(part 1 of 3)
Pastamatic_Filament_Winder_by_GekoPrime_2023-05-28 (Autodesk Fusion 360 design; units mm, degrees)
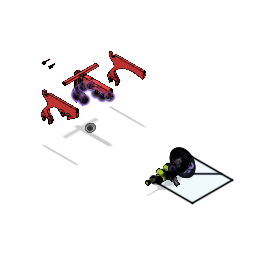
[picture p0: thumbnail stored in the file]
description: Spur Gear; Module: 2.0; Num Teeth: 20; Pressure Angle: 20.0; Backlash: 0.00 mm
description: Spur Gear; Module: 2.0; Num Teeth: 40; Pressure Angle: 20.0; Backlash: 0.00 mm
description: Spur Gear; Module: 2.0; Num Teeth: 10; Pressure Angle: 20.0; Backlash: 0.00 mm
description: Spur Gear; Module: 2.0; Num Teeth: 50; Pressure Angle: 20.0; Backlash: 0.00 mm
description: Spur Gear; Module: 2.0; Num Teeth: 30; Pressure Angle: 20.0; Backlash: 0.00 mm
parameter "bearing_od" = 22
parameter "bearing_id" = 8
parameter "bearing_z" = 7
parameter "spool_id_min" = 50
parameter "spool_id_max" = 60
parameter "spool_od_max" = 250
parameter "spool_z_max" = 120
parameter "ptfe_od" = 4
parameter "drive_span" = 6.65 (= "clearance_loose + 1 / 4 * 1 in")
parameter "overhang_angle" = 45
parameter "spool_z_min" = 50
parameter "spur_gear_z" = 7 (= "bearing_z")
parameter "spur_gear_diameter_medium" = 40
parameter "axle_od" = 26 (= "bearing_od + 2 * wall_thickness")
parameter "leadscrew_pitch" = 30 (= "spool_inner_z_bambu / leadscrew_turns")
parameter "leadscrew_tooth_height" = 3.3333 (= "leadscrew_od / 6")
parameter "clearance_loose" = 0.3
parameter "screw_od" = 22 (= "axle_od - 2 * wall_thickness")
parameter "screw_pitch" = 22 (= "screw_od")
parameter "screw_id" = 18 (= "screw_od - 2 * wall_thickness")
parameter "wall_thickness" = 2
parameter "washer_z" = 0.3 (= "clearance_loose")
parameter "leadscrew_angle" = 64.477 (= "atan(PI * leadscrew_od / leadscrew_pitch)")
parameter "washer_radial_thichness" = 1
parameter "internal_cavity_thickness" = 1
parameter "clearance_tight" = 0.01
parameter "buildplate_limit" = 240
parameter "spur_gear_diameter_small" = 20
parameter "stack_unit" = 11.6 (= "bearing_z + 2 * washer_z + 2 * wall_thickness")
parameter "fillet_radius" = 2 (= "wall_thickness")
parameter "spur_gear_diameter_large" = 100
parameter "ground_clearance" = 20
parameter "drive_depth" = 25.4
parameter "spool_id_bambu" = 54
parameter "spool_od_bambu" = 200
parameter "spool_inner_z_bambu" = 60
parameter "leadscrew_od" = 20
parameter "crossbar_od" = 20 (= "ground_clearance")
parameter "leadscrew_length" = 200
parameter "leadscrew_center_position" = 68.928
parameter "spur_gear_clearance" = 4
parameter "motor_mounting_circle" = 31
parameter "washer_taper" = -45
parameter "spool_interface_z_bambu" = 62
sketch "Sketch1" plane through (0, 0, 0) normal (0, 0, 1) x axis (1, 0, 0)
  circle C1 centre (0, 0) radius 7.5492
extrude "Extrude1" new body sketch "Sketch1" along normal blind 7 bodies "spur_gear_10t_7mm"
sketch "Sketch2" plane through (0, 0, 0) normal (0, 0, 1) x axis (1, 0, 0)
  curve K1 (11.9856, -0.5875) -> (9.2583, -1.6082)
  curve K2 (11.9856, 0.5875) -> (9.2583, 1.6082)
  line L1 (9.2583, -1.6082) -> (7.428, -1.292)
  line L2 (9.2583, 1.6082) -> (7.428, 1.292)
  line L3 (7.428, 1.292) -> (7.428, -1.292)
  arc A1 centre (0, 0) radius 12 clockwise from (11.9856, 0.5875) to (11.9856, -0.5875)
extrude "Extrude2" add sketch "Sketch2" along normal blind 7
fillet "Fillet1" radius 1
circular_pattern "C-Pattern1" countU 10 TotalAngle 360
sketch "Sketch3" plane through (0, 0, 0) normal (0, 0, 1) x axis (1, 0, 0)
  circle C1 centre (0, 0) radius 10
sketch "Sketch1" plane through (0, 0, 0) normal (0, 0, 1) x axis (1, 0, 0)
  circle C1 centre (0, 0) radius 17.5492
  circle C2 centre (0, 0) radius 11
extrude "Extrude1" new body sketch "Sketch1" along normal blind 7 bodies "idler"
sketch "Sketch2" plane through (0, 0, 0) normal (0, 0, 1) x axis (1, 0, 0)
  curve K1 (21.989, -0.6948) -> (18.7119, -1.7536)
  curve K2 (21.989, 0.6948) -> (18.7119, 1.7536)
  line L1 (18.7119, -1.7536) -> (17.4627, -1.6375)
  line L2 (18.7119, 1.7536) -> (17.4627, 1.6375)
  line L3 (17.4627, 1.6375) -> (17.4627, -1.6375)
  arc A1 centre (0, 0) radius 22 clockwise from (21.989, 0.6948) to (21.989, -0.6948)
extrude "Extrude2" add sketch "Sketch2" along normal blind 7
fillet "Fillet1" radius 1
circular_pattern "C-Pattern1" countU 20 TotalAngle 360
sketch "Sketch3" plane through (0, 0, 0) normal (0, 0, 1) x axis (1, 0, 0)
  circle C1 centre (0, 0) radius 20
sketch "Sketch4" plane through (0, 0, 0) normal (1, 0, 0) x axis (0, 0, -1)
  line L1 (0, -22) -> (0, -21.989)
  line L2 (-7, -22) -> (-7, -21.989)
  line L3 (0, 21.989) -> (0, 22)
  line L4 (-7, 21.989) -> (-7, 22)
  line L5 (-7, -22) -> (0, -22)
  line L6 (-7, 22) -> (-7, -21.989)
  line L7 (0, -21.989) -> (0, 21.989)
  line L8 (-7, 19.652) -> (-4.663, 21.989)
  line L9 (0, 19.652) -> (-2.326, 22)
  line L10 (0, 0) -> (-7, 0.0055)
  line L11 (-3.5, 22) -> (-3.5, 19.652)
  line L12 (0, 19.652) -> (-3.5, 19.652)
  line L13 (-7, 19.652) -> (-3.5, 19.652)
  line L14 (-2.326, 22) -> (-4.663, 21.989)
  line L15 (0, 22) -> (-2.326, 22)
  line L16 (-7, 21.989) -> (-4.663, 21.989)
  point P4 (-7, -21.989)
  point P10 (-7, -21.989)
  point P9 (-7, 22)
  point P11 (-7, 22)
  point P6 (0, 21.989)
  point P12 (0, 21.989)
  point P2 (0, -21.989)
  point P13 (0, -21.989)
  point P15 (-7, 19.652)
  point P17 (0, 19.652)
  point P18 (-7, 0.0055)
  point P1 (0, 0)
  point P19 (0, 0)
  point P8 (0, 22)
  point P22 (0, 22)
  point P7 (-7, 21.989)
  point P23 (-7, 21.989)
  coincident P4 P10
  coincident P9 P11
  coincident P6 P12
  coincident P2 P13
  coincident L6 P15
  coincident L7 P17
  midpoint L6 P18
  coincident P1 P19
  equal L8 L9
  perpendicular L7 L12
  perpendicular L6 L13
  perpendicular L11 L12
  coincident P8 P22
  coincident P7 P23
  perpendicular L7 L15
  perpendicular L6 L16
  equal L12 L13
  equal L14 L16
  dimension "d1268" angle L6 L8 = 45
revolve "Revolve1" sketch "Sketch4" AlongAngle 360
chamfer "Chamfer1" distance 1
sketch "Sketch1" plane through (0, 0, 0) normal (0, 0, 1) x axis (1, 0, 0)
  circle C1 centre (0, 0) radius 37.5492
  circle C2 centre (0, 0) radius 11
extrude "Extrude1" new body sketch "Sketch1" along normal blind 7 bodies "spur_gear_40t_7mm"
sketch "Sketch2" plane through (0, 0, 0) normal (0, 0, 1) x axis (1, 0, 0)
  curve K1 (41.9931, -0.7606) -> (37.5326, -2.0353)
  curve K2 (41.9931, 0.7606) -> (37.5326, 2.0353)
  line L1 (37.5326, -2.0353) -> (37.4841, -2.0332)
  line L2 (37.5326, 2.0353) -> (37.4841, 2.0332)
  line L3 (37.4841, 2.0332) -> (37.4841, -2.0332)
  arc A1 centre (0, 0) radius 42 clockwise from (41.9931, 0.7606) to (41.9931, -0.7606)
extrude "Extrude2" add sketch "Sketch2" along normal blind 7
fillet "Fillet1" radius 1
circular_pattern "C-Pattern1" countU 40 TotalAngle 360
sketch "Sketch3" plane through (0, 0, 0) normal (0, 0, 1) x axis (1, 0, 0)
  circle C1 centre (0, 0) radius 40
sketch "Sketch1" plane through (0, 0, 0) normal (0, 0, 1) x axis (1, 0, 0)
  circle C1 centre (0, 0) radius 47.5492
extrude "Extrude1" new body sketch "Sketch1" along normal blind 7 bodies "spur_gear_50t_7mm"
sketch "Sketch2" plane through (0, 0, 0) normal (0, 0, 1) x axis (1, 0, 0)
  curve K1 (51.9942, -0.7754) -> (46.9342, -2.1756)
  curve K2 (51.9942, 0.7754) -> (46.9342, 2.1756)
  line L1 (46.9342, -2.1756) -> (46.9342, 2.1756)
  arc A1 centre (0, 0) radius 52 clockwise from (51.9942, 0.7754) to (51.9942, -0.7754)
extrude "Extrude2" add sketch "Sketch2" along normal blind 7
fillet "Fillet1" radius 1
circular_pattern "C-Pattern1" countU 50 TotalAngle 360
sketch "Sketch3" plane through (0, 0, 0) normal (0, 0, 1) x axis (1, 0, 0)
  circle C1 centre (0, 0) radius 50
sketch "Sketch5" plane through (0, 0, 0) normal (1, 0, 0) x axis (0, 0, -1)
  line L1 (-7, 51.9403) -> (0, 51.9403)
  line L2 (0, 49.607) -> (-3.5, 53.107)
  line L3 (0, 51.9403) -> (0, 49.607)
  line L4 (-7, 49.607) -> (-7, 51.9403)
  line L5 (-3.5, 53.107) -> (-7, 49.607)
  line L6 (-7, 53.107) -> (-7, 51.9403)
  line L7 (0, 53.107) -> (-7, 53.107)
  line L8 (0, 51.9403) -> (0, 53.107)
  point P2 (0, 51.9403)
  point P6 (0, 51.9403)
  point P3 (-7, 51.9403)
  point P7 (-7, 51.9403)
  point P10 (-7, 51.9403)
  point P13 (0, 51.9403)
  point P14 (-4.6667, 51.9403)
  point P15 (-2.3333, 51.9403)
  point P9 (-3.5, 53.107)
  point P4 (-3.5, 53.107)
  coincident P2 P6
  coincident P3 P7
  perpendicular L1 L4
  perpendicular L1 L3
  equal L2 L5
  equal L3 L4
  coincident P3 P10
  perpendicular L1 L6
  coincident P2 P13
  perpendicular L1 L8
  coincident L5 P14
  coincident L1 P14
  coincident L1 P15
  coincident L2 P15
  perpendicular L6 L7
  coincident P9 L7
  coincident P4 L7
  coincident P4 P9
  dimension "d1416" angle L4 L5 = 45
  dimension "d1419" distance P14 P15 = 2.3333 (= "bearing_z / 3")
revolve "Revolve1" sketch "Sketch5" AlongAngle 360
sketch "Sketch1" plane through (0, 0, 0) normal (0, 0, 1) x axis (1, 0, 0)
  line L1 (1.6583, -2.5) -> (-1.6583, -2.5)
  line L2 (4, 3) -> (-5, 3)
  circle C1 centre (0, 0) radius 7.5492
  circle C2 centre (0, 0) radius 3
  point P4 (-1.6583, -2.5)
  point P5 (1.6583, -2.5)
  concentric C1 C2
  coincident C2 P4
  coincident C2 P5
  horizontal L1
  horizontal L2
  tangent C2 L2
  dimension "d1565" distance L1 L2 = 5.5
  dimension "d1566" diameter C2 = 6
extrude "Extrude1" new body sketch "Sketch1" profile of C1 C2 L1 along normal blind 14 named "d988_1" bodies "spur_gear_10t_14mm_6mmD"
sketch "Sketch2" plane through (0, 0, 0) normal (0, 0, 1) x axis (1, 0, 0)
  curve K1 (11.9856, -0.5875) -> (9.2583, -1.6082)
  curve K2 (11.9856, 0.5875) -> (9.2583, 1.6082)
  line L1 (9.2583, -1.6082) -> (7.428, -1.292)
  line L2 (9.2583, 1.6082) -> (7.428, 1.292)
  line L3 (7.428, 1.292) -> (7.428, -1.292)
  arc A1 centre (0, 0) radius 12 clockwise from (11.9856, 0.5875) to (11.9856, -0.5875)
extrude "Extrude2" add sketch "Sketch2" along normal blind 14 named "d990_1"
fillet "Fillet1" radius 1 named "d993_1"
circular_pattern "C-Pattern1" countU 10 named "d994_1" TotalAngle 360 named "d995_1"
sketch "Sketch3" plane through (0, 0, 0) normal (0, 0, 1) x axis (1, 0, 0)
  circle C1 centre (0, 0) radius 10
sketch "Sketch4" plane through (0, 0, 0) normal (0, 1, 0) x axis (1, 0, 0)
  line L1 (0, 0) -> (0, -14)
  line L2 (9.6667, 0) -> (0, 0)
  line L3 (12, -2.3333) -> (9.6667, 0)
  line L4 (12, -11.6667) -> (12, -2.3333)
  line L5 (9.6667, -14) -> (12, -11.6667)
  line L6 (0, -14) -> (9.6667, -14)
  line L7 (0, -7) -> (12, -7)
  point P1 (0, 0)
  point P3 (0, 0)
  point P8 (12, -7)
  point P9 (0, -7)
  point P2 (0, -14)
  point P5 (12, -2.3333)
  point P6 (12, -11.6667)
  coincident P1 P3
  vertical L1
  perpendicular L1 L2
  perpendicular L2 L4
  perpendicular L1 L6
  equal L3 L5
  midpoint L4 P8
  midpoint L1 P9
  perpendicular L4 L7
  dimension "d1567" distance P2 P3 = 14
  dimension "d1568" distance L1 L4 = 12 (= "spur_gear_diameter_small / 2 + spur_gear_clearance / 2")
  dimension "d1569" angle L5 L6 = 45
  dimension "d1570" distance P5 P6 = 9.3333 (= "7 mm + ( 7 / 3 ) * 1 mm")
revolve "Revolve1" sketch "Sketch4" AlongAngle 360
sketch "Sketch1" plane through (0, 0, 0) normal (0, 0, 1) x axis (1, 0, 0)
  circle C1 centre (0, 0) radius 27.5492
extrude "Extrude1" new body sketch "Sketch1" along normal blind 7 bodies "spur_gear_30t_7mm"
sketch "Sketch2" plane through (0, 0, 0) normal (0, 0, 1) x axis (1, 0, 0)
  curve K1 (31.9915, -0.7373) -> (28.127, -1.8948)
  curve K2 (31.9915, 0.7373) -> (28.127, 1.8948)
  line L1 (28.127, -1.8948) -> (27.4769, -1.8517)
  line L2 (28.127, 1.8948) -> (27.4769, 1.8517)
  line L3 (27.4769, 1.8517) -> (27.4769, -1.8517)
  arc A1 centre (0, 0) radius 32 clockwise from (31.9915, 0.7373) to (31.9915, -0.7373)
extrude "Extrude2" add sketch "Sketch2" along normal blind 7
fillet "Fillet1" radius 1
circular_pattern "C-Pattern1" countU 30 TotalAngle 360
sketch "Sketch3" plane through (0, 0, 0) normal (0, 0, 1) x axis (1, 0, 0)
  circle C1 centre (0, 0) radius 30
copy_paste_bodies "CopyPasteBodies3"
copy_paste_bodies "CopyPasteBodies2"
align "Align1"
move "Move1" TranslateX 0 TranslateY 0 TranslateZ -4 (= "-2 * wall_thickness")
sketch "Sketch1" plane through (0, 0, 7) normal (0, 0, 1) x axis (1, 0, 0)
  curve K1 (27.4076, 2.7893) -> (28.3353, 1.8928)
  curve K2 (31.9915, 0.7373) -> (28.3353, 1.8928)
  curve K3 (28.3353, -1.8928) -> (31.9915, -0.7373)
  curve K4 (28.3353, -1.8928) -> (27.4076, -2.7893)
  curve K5 (27.3886, -2.97) -> (28.1096, -4.0398)
  curve K6 (31.4457, -5.9302) -> (28.1096, -4.0398)
  curve K7 (27.3226, -7.7427) -> (31.1391, -7.3726)
  curve K8 (27.3226, -7.7427) -> (26.2288, -8.4267)
  curve K9 (26.1726, -8.5996) -> (26.6554, -9.7959)
  curve K10 (29.5256, -12.3385) -> (26.6554, -9.7959)
  curve K11 (25.1157, -13.2541) -> (28.9258, -13.6857)
  curve K12 (25.1157, -13.2541) -> (23.9036, -13.6958)
  curve K13 (23.8127, -13.8532) -> (24.0363, -15.1238)
  curve K14 (26.3151, -18.2076) -> (24.0363, -15.1238)
  curve K15 (21.8112, -18.1864) -> (25.4483, -19.4007)
  curve K16 (21.8112, -18.1864) -> (20.5337, -18.3664)
  curve K17 (20.4121, -18.5015) -> (20.3666, -19.7907)
  curve K18 (21.9544, -23.2809) -> (20.3666, -19.7907)
  curve K19 (17.5534, -22.3237) -> (20.8585, -24.2677)
  curve K20 (17.5534, -22.3237) -> (16.2665, -22.2342)
  curve K21 (16.1194, -22.3411) -> (15.8068, -23.5927)
  curve K22 (16.6343, -27.3368) -> (15.8068, -23.5927)
  curve K23 (12.5284, -25.4855) -> (15.3572, -28.0741)
  curve K24 (12.5284, -25.4855) -> (11.2882, -25.1303)
  curve K25 (11.1222, -25.2043) -> (10.5562, -26.3636)
  curve K26 (10.5872, -30.1979) -> (10.5562, -26.3636)
  curve K27 (6.9559, -27.5334) -> (9.1847, -30.6536)
  curve K28 (6.9559, -27.5334) -> (5.8167, -26.9281)
  curve K29 (5.6389, -26.9659) -> (4.8443, -27.9822)
  curve K30 (4.0773, -31.7392) -> (4.8443, -27.9822)
  curve K31 (1.0794, -28.3779) -> (2.6107, -31.8933)
  curve K32 (1.0794, -28.3779) -> (0.0909, -27.5491)
  curve K33 (-0.0909, -27.5491) -> (-1.0794, -28.3779)
  curve K34 (-2.6107, -31.8933) -> (-1.0794, -28.3779)
  curve K35 (-4.8443, -27.9822) -> (-4.0773, -31.7392)
  curve K36 (-4.8443, -27.9822) -> (-5.6389, -26.9659)
  curve K37 (-5.8167, -26.9281) -> (-6.9559, -27.5334)
  curve K38 (-9.1847, -30.6536) -> (-6.9559, -27.5334)
  curve K39 (-10.5562, -26.3636) -> (-10.5872, -30.1979)
  curve K40 (-10.5562, -26.3636) -> (-11.1222, -25.2043)
  curve K41 (-11.2882, -25.1303) -> (-12.5284, -25.4855)
  curve K42 (-15.3572, -28.0741) -> (-12.5284, -25.4855)
  curve K43 (-15.8068, -23.5927) -> (-16.6343, -27.3368)
  curve K44 (-15.8068, -23.5927) -> (-16.1194, -22.3411)
  curve K45 (-16.2665, -22.2342) -> (-17.5534, -22.3237)
  curve K46 (-20.8585, -24.2677) -> (-17.5534, -22.3237)
  curve K47 (-20.3666, -19.7907) -> (-21.9544, -23.2809)
  curve K48 (-20.3666, -19.7907) -> (-20.4121, -18.5015)
  curve K49 (-20.5337, -18.3664) -> (-21.8112, -18.1864)
  curve K50 (-25.4483, -19.4007) -> (-21.8112, -18.1864)
  curve K51 (-24.0363, -15.1238) -> (-26.3151, -18.2076)
  curve K52 (-24.0363, -15.1238) -> (-23.8127, -13.8532)
  curve K53 (-23.9036, -13.6958) -> (-25.1157, -13.2541)
  curve K54 (-28.9258, -13.6857) -> (-25.1157, -13.2541)
  curve K55 (-26.6554, -9.7959) -> (-29.5256, -12.3385)
  curve K56 (-26.6554, -9.7959) -> (-26.1726, -8.5996)
  curve K57 (-26.2288, -8.4267) -> (-27.3226, -7.7427)
  curve K58 (-31.1391, -7.3726) -> (-27.3226, -7.7427)
  curve K59 (-28.1096, -4.0398) -> (-31.4457, -5.9302)
  curve K60 (-28.1096, -4.0398) -> (-27.3886, -2.97)
  curve K61 (-27.4076, -2.7893) -> (-28.3353, -1.8928)
  curve K62 (-31.9915, -0.7373) -> (-28.3353, -1.8928)
  curve K63 (-28.3353, 1.8928) -> (-31.9915, 0.7373)
  curve K64 (-28.3353, 1.8928) -> (-27.4076, 2.7893)
  curve K65 (-27.3886, 2.97) -> (-28.1096, 4.0398)
  curve K66 (-31.4457, 5.9302) -> (-28.1096, 4.0398)
  curve K67 (-27.3226, 7.7427) -> (-31.1391, 7.3726)
  curve K68 (-27.3226, 7.7427) -> (-26.2288, 8.4267)
  curve K69 (-26.1726, 8.5996) -> (-26.6554, 9.7959)
  curve K70 (-29.5256, 12.3385) -> (-26.6554, 9.7959)
  curve K71 (-25.1157, 13.2541) -> (-28.9258, 13.6857)
  curve K72 (-25.1157, 13.2541) -> (-23.9036, 13.6958)
  curve K73 (-23.8127, 13.8532) -> (-24.0363, 15.1238)
  curve K74 (-26.3151, 18.2076) -> (-24.0363, 15.1238)
  curve K75 (-21.8112, 18.1864) -> (-25.4483, 19.4007)
  curve K76 (-21.8112, 18.1864) -> (-20.5337, 18.3664)
  curve K77 (-20.4121, 18.5015) -> (-20.3666, 19.7907)
  curve K78 (-21.9544, 23.2809) -> (-20.3666, 19.7907)
  curve K79 (-17.5534, 22.3237) -> (-20.8585, 24.2677)
  curve K80 (-17.5534, 22.3237) -> (-16.2665, 22.2342)
  curve K81 (-16.1194, 22.3411) -> (-15.8068, 23.5927)
  curve K82 (-16.6343, 27.3368) -> (-15.8068, 23.5927)
  curve K83 (-12.5284, 25.4855) -> (-15.3572, 28.0741)
  curve K84 (-12.5284, 25.4855) -> (-11.2882, 25.1303)
  curve K85 (-11.1222, 25.2043) -> (-10.5562, 26.3636)
  curve K86 (-10.5872, 30.1979) -> (-10.5562, 26.3636)
  curve K87 (-6.9559, 27.5334) -> (-9.1847, 30.6536)
  curve K88 (-6.9559, 27.5334) -> (-5.8167, 26.9281)
  curve K89 (-5.6389, 26.9659) -> (-4.8443, 27.9822)
  curve K90 (-4.0773, 31.7392) -> (-4.8443, 27.9822)
  curve K91 (-1.0794, 28.3779) -> (-2.6107, 31.8933)
  curve K92 (-1.0794, 28.3779) -> (-0.0909, 27.5491)
  curve K93 (0.0909, 27.5491) -> (1.0794, 28.3779)
  curve K94 (2.6107, 31.8933) -> (1.0794, 28.3779)
  curve K95 (4.8443, 27.9822) -> (4.0773, 31.7392)
  curve K96 (4.8443, 27.9822) -> (5.6389, 26.9659)
  curve K97 (5.8167, 26.9281) -> (6.9559, 27.5334)
  curve K98 (9.1847, 30.6536) -> (6.9559, 27.5334)
  curve K99 (10.5562, 26.3636) -> (10.5872, 30.1979)
  curve K100 (10.5562, 26.3636) -> (11.1222, 25.2043)
  curve K101 (11.2882, 25.1303) -> (12.5284, 25.4855)
  curve K102 (15.3572, 28.0741) -> (12.5284, 25.4855)
  curve K103 (15.8068, 23.5927) -> (16.6343, 27.3368)
  curve K104 (15.8068, 23.5927) -> (16.1194, 22.3411)
  curve K105 (16.2665, 22.2342) -> (17.5534, 22.3237)
  curve K106 (20.8585, 24.2677) -> (17.5534, 22.3237)
  curve K107 (20.3666, 19.7907) -> (21.9544, 23.2809)
  curve K108 (20.3666, 19.7907) -> (20.4121, 18.5015)
  curve K109 (20.5337, 18.3664) -> (21.8112, 18.1864)
  curve K110 (25.4483, 19.4007) -> (21.8112, 18.1864)
  curve K111 (24.0363, 15.1238) -> (26.3151, 18.2076)
  curve K112 (24.0363, 15.1238) -> (23.8127, 13.8532)
  curve K113 (23.9036, 13.6958) -> (25.1157, 13.2541)
  curve K114 (28.9258, 13.6857) -> (25.1157, 13.2541)
  curve K115 (26.6554, 9.7959) -> (29.5256, 12.3385)
  curve K116 (26.6554, 9.7959) -> (26.1726, 8.5996)
  curve K117 (26.2288, 8.4267) -> (27.3226, 7.7427)
  curve K118 (31.1391, 7.3726) -> (27.3226, 7.7427)
  curve K119 (28.1096, 4.0398) -> (31.4457, 5.9302)
  curve K120 (28.1096, 4.0398) -> (27.3886, 2.97)
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  point P1 (0, 0)
  point P2 (0, 0)
  coincident P1 P2
  dimension "d1501" distance = 2 (= "wall_thickness")
  dimension "d1748" diameter = 50.3377 (= "spur_gear_conversion_diameter - 2 * spur_gear_clearance - 2 * wall_thickness")
  dimension "d1749" distance = 2 (= "wall_thickness")
  dimension "d1750" distance = 2 (= "wall_thickness")
  dimension "d1751" angle = 36 (= "( 360 / 10 ) * 1 deg")
extrude "Extrude7" cut sketch "Sketch1" no distance stored
fillet "Fillet2" radius 2 (= "wall_thickness")
chamfer "Chamfer3" distance 0.5 (= "wall_thickness / 4")
circular_pattern "C-Pattern3" countU 10 TotalAngle 360
loft "Loft2" sketch "Sketch1" bodies "spur_gear_30t_7mm"
extrude "Extrude5" cut sketch "Sketch1" no distance stored
sketch "Sketch2" plane through (0, 0, -4) normal (0, 0, -1) x axis (-1, 0, 0)
  line L1 (-4.3904, -8.3082) -> (-3.9672, -7.5055)
  curve K1 (-4.2625, -11.2175) -> (-4.3904, -8.3082)
  curve K2 (-3.145, -11.5805) -> (-1.3315, -9.3021)
  line L2 (-1.2021, -8.404) -> (-1.3315, -9.3021)
  line L3 (1.3315, -9.3021) -> (1.2021, -8.404)
  curve K3 (3.145, -11.5805) -> (1.3315, -9.3021)
  curve K4 (4.2625, -11.2175) -> (4.3904, -8.3082)
  line L4 (3.9672, -7.5055) -> (4.3904, -8.3082)
  line L5 (6.5449, -6.7429) -> (5.9123, -6.0924)
  curve K5 (9.3513, -7.5202) -> (6.5449, -6.7429)
  curve K6 (10.0419, -6.5697) -> (8.4354, -4.1409)
  line L6 (7.6212, -3.7403) -> (8.4354, -4.1409)
  line L7 (9.2583, -1.6082) -> (8.3641, -1.4537)
  curve K7 (11.9856, -0.5875) -> (9.2583, -1.6082)
  curve K8 (11.9856, 0.5875) -> (9.2583, 1.6082)
  line L8 (8.3641, 1.4537) -> (9.2583, 1.6082)
  line L9 (8.4354, 4.1409) -> (7.6212, 3.7403)
  curve K9 (10.0419, 6.5697) -> (8.4354, 4.1409)
  curve K10 (9.3513, 7.5202) -> (6.5449, 6.7429)
  line L10 (5.9123, 6.0924) -> (6.5449, 6.7429)
  line L11 (4.3904, 8.3082) -> (3.9672, 7.5055)
  curve K11 (4.2625, 11.2175) -> (4.3904, 8.3082)
  curve K12 (3.145, 11.5805) -> (1.3315, 9.3021)
  line L12 (1.2021, 8.404) -> (1.3315, 9.3021)
  line L13 (-1.3315, 9.3021) -> (-1.2021, 8.404)
  curve K13 (-3.145, 11.5805) -> (-1.3315, 9.3021)
  curve K14 (-4.2625, 11.2175) -> (-4.3904, 8.3082)
  line L14 (-3.9672, 7.5055) -> (-4.3904, 8.3082)
  line L15 (-6.5449, 6.7429) -> (-5.9123, 6.0924)
  curve K15 (-9.3513, 7.5202) -> (-6.5449, 6.7429)
  curve K16 (-10.0419, 6.5697) -> (-8.4354, 4.1409)
  line L16 (-7.6212, 3.7403) -> (-8.4354, 4.1409)
  line L17 (-9.2583, 1.6082) -> (-8.3641, 1.4537)
  curve K17 (-11.9856, 0.5875) -> (-9.2583, 1.6082)
  curve K18 (-11.9856, -0.5875) -> (-9.2583, -1.6082)
  line L18 (-8.3641, -1.4537) -> (-9.2583, -1.6082)
  line L19 (-8.4354, -4.1409) -> (-7.6212, -3.7403)
  curve K19 (-10.0419, -6.5697) -> (-8.4354, -4.1409)
  curve K20 (-9.3513, -7.5202) -> (-6.5449, -6.7429)
  line L20 (-5.9123, -6.0924) -> (-6.5449, -6.7429)
  arc A1 centre (-4.8518, -7.0391) radius 1 clockwise from (-4.2842, -6.2158) to (-3.9672, -7.5055)
  arc A2 centre (0, 0) radius 12 clockwise from (-3.145, -11.5805) to (-4.2625, -11.2175)
  arc A3 centre (-0.2123, -8.5466) radius 1 clockwise from (-1.2021, -8.404) to (-0.1875, -7.5469)
  arc A4 centre (0, 0) radius 7.5492 clockwise from (0.1875, -7.5469) to (-0.1875, -7.5469)
  arc A5 centre (0.2123, -8.5466) radius 1 clockwise from (0.1875, -7.5469) to (1.2021, -8.404)
  arc A6 centre (0, 0) radius 12 clockwise from (4.2625, -11.2175) to (3.145, -11.5805)
  arc A7 centre (4.8518, -7.0391) radius 1 clockwise from (3.9672, -7.5055) to (4.2842, -6.2158)
  arc A8 centre (0, 0) radius 7.5492 clockwise from (4.5876, -5.9953) to (4.2842, -6.2158)
  arc A9 centre (5.1953, -6.7895) radius 1 clockwise from (4.5876, -5.9953) to (5.9123, -6.0924)
  arc A10 centre (0, 0) radius 12 clockwise from (10.0419, -6.5697) to (9.3513, -7.5202)
  arc A11 centre (8.0626, -2.843) radius 1 clockwise from (7.6212, -3.7403) to (7.1196, -2.5104)
  arc A12 centre (0, 0) radius 7.5492 clockwise from (7.2354, -2.1538) to (7.1196, -2.5104)
  arc A13 centre (8.1939, -2.4391) radius 1 clockwise from (7.2354, -2.1538) to (8.3641, -1.4537)
  arc A14 centre (0, 0) radius 12 clockwise from (11.9856, 0.5875) to (11.9856, -0.5875)
  arc A15 centre (8.1939, 2.4391) radius 1 clockwise from (8.3641, 1.4537) to (7.2354, 2.1538)
  arc A16 centre (0, 0) radius 7.5492 clockwise from (7.1196, 2.5104) to (7.2354, 2.1538)
  arc A17 centre (8.0626, 2.843) radius 1 clockwise from (7.1196, 2.5104) to (7.6212, 3.7403)
  arc A18 centre (0, 0) radius 12 clockwise from (9.3513, 7.5202) to (10.0419, 6.5697)
  arc A19 centre (5.1953, 6.7895) radius 1 clockwise from (5.9123, 6.0924) to (4.5876, 5.9953)
  arc A20 centre (0, 0) radius 7.5492 clockwise from (4.2842, 6.2158) to (4.5876, 5.9953)
  arc A21 centre (4.8518, 7.0391) radius 1 clockwise from (4.2842, 6.2158) to (3.9672, 7.5055)
  arc A22 centre (0, 0) radius 12 clockwise from (3.145, 11.5805) to (4.2625, 11.2175)
  arc A23 centre (0.2123, 8.5466) radius 1 clockwise from (1.2021, 8.404) to (0.1875, 7.5469)
  arc A24 centre (0, 0) radius 7.5492 clockwise from (-0.1875, 7.5469) to (0.1875, 7.5469)
  arc A25 centre (-0.2123, 8.5466) radius 1 clockwise from (-0.1875, 7.5469) to (-1.2021, 8.404)
  arc A26 centre (0, 0) radius 12 clockwise from (-4.2625, 11.2175) to (-3.145, 11.5805)
  arc A27 centre (-4.8518, 7.0391) radius 1 clockwise from (-3.9672, 7.5055) to (-4.2842, 6.2158)
  arc A28 centre (0, 0) radius 7.5492 clockwise from (-4.5876, 5.9953) to (-4.2842, 6.2158)
  arc A29 centre (-5.1953, 6.7895) radius 1 clockwise from (-4.5876, 5.9953) to (-5.9123, 6.0924)
  arc A30 centre (0, 0) radius 12 clockwise from (-10.0419, 6.5697) to (-9.3513, 7.5202)
  arc A31 centre (-8.0626, 2.843) radius 1 clockwise from (-7.6212, 3.7403) to (-7.1196, 2.5104)
  arc A32 centre (0, 0) radius 7.5492 clockwise from (-7.2354, 2.1538) to (-7.1196, 2.5104)
  arc A33 centre (-8.1939, 2.4391) radius 1 clockwise from (-7.2354, 2.1538) to (-8.3641, 1.4537)
  arc A34 centre (0, 0) radius 12 clockwise from (-11.9856, -0.5875) to (-11.9856, 0.5875)
  arc A35 centre (-8.1939, -2.4391) radius 1 clockwise from (-8.3641, -1.4537) to (-7.2354, -2.1538)
  arc A36 centre (0, 0) radius 7.5492 clockwise from (-7.1196, -2.5104) to (-7.2354, -2.1538)
  arc A37 centre (-8.0626, -2.843) radius 1 clockwise from (-7.1196, -2.5104) to (-7.6212, -3.7403)
  arc A38 centre (0, 0) radius 12 clockwise from (-9.3513, -7.5202) to (-10.0419, -6.5697)
  arc A39 centre (-5.1953, -6.7895) radius 1 clockwise from (-5.9123, -6.0924) to (-4.5876, -5.9953)
  arc A40 centre (0, 0) radius 7.5492 clockwise from (-4.2842, -6.2158) to (-4.5876, -5.9953)
  circle C1 centre (0, 0) radius 4.15
  concentric A2 C1
  dimension "d1622" diameter C1 = 8.3 (= "bearing_id + clearance_loose")
loft "Loft3" sketch "Sketch2" + "Sketch1" Start TakeOff Angle 0
sketch "Sketch3" plane through (0, 0, 0) normal (0, 1, 0) x axis (1, 0, 0)
  line L1 (0, -14) -> (-32, -14)
  line L2 (0, 4) -> (0, -14)
  line L3 (-12, 4) -> (0, 4)
  line L4 (-12, -3) -> (-12, 4)
  line L5 (-32, -7) -> (-12, -3)
  line L6 (-32, -14) -> (-32, -7)
  line L7 (-29.6667, -14) -> (-32, -11.6667)
  line L8 (-12, -7) -> (-32, -7)
  line L9 (-12, -3) -> (-12, -7)
  line L10 (-29.6667, -7) -> (-32, -9.3333)
  line L11 (-9.6667, 4) -> (-12, 1.6667)
  point P7 (-32, -7)
  point P8 (0, -7)
  point P9 (-32, -11.6667)
  point P10 (-29.6667, -14)
  point P12 (-32, -9.3333)
  point P13 (-29.6667, -7)
  point P14 (-12, 1.6667)
  point P15 (-9.6667, 4)
  point P5 (-12, 4)
  point P6 (-12, -3)
  point P2 (-32, -14)
  point P4 (0, 4)
  point P3 (0, -14)
  horizontal L1
  perpendicular L1 L2
  perpendicular L2 L3
  perpendicular L3 L4
  perpendicular L1 L6
  horizontal P7 P8
  coincident L2 P8
  coincident L6 P9
  coincident L1 P10
  perpendicular L6 L8
  perpendicular L8 L9
  coincident L6 P12
  coincident L8 P13
  coincident L4 P14
  coincident L3 P15
  equal L7 L10
  equal L10 L11
  perpendicular L7 L10
  parallel L10 L11
  dimension "d1626" distance P5 P6 = 7 (= "bearing_z")
  dimension "d1627" distance P2 P7 = 7 (= "bearing_z")
  dimension "d1628" distance P6 P7 = 4 (= "2 * wall_thickness")
  dimension "d1629" distance P4 P5 = 12 (= "spur_gear_diameter_small / 2 + spur_gear_clearance / 2")
  dimension "d1630" distance P2 P3 = 32 (= "( 60 / 2 ) * 1 mm + spur_gear_clearance / 2")
  dimension "d1631" angle L1 L7 = 45
  dimension "d1632" distance P9 P12 = 2.3333 (= "bearing_z / 3")
revolve "Revolve1" sketch "Sketch3" AlongAngle 360
chamfer "Chamfer2" distance 0.5 (= "wall_thickness / 4")
sketch "Sketch1" plane through (0, 0, 0) normal (0, 0, 1) x axis (1, 0, 0)
  line L1 (0, 5) -> (0, -5)
  line L2 (24.6, -10.3) -> (24.6, 10.3)
  line L3 (49.22, -10.3) -> (24.6, -10.3)
  line L4 (49.22, 10.3) -> (49.22, -10.3)
  line L5 (24.6, 10.3) -> (49.22, 10.3)
  line L6 (49.21, -10.29) -> (24.61, -10.29)
  line L7 (49.21, 10.29) -> (49.21, -10.29)
  line L8 (24.61, 10.29) -> (49.21, 10.29)
  line L9 (24.61, -10.29) -> (24.61, 10.29)
  line L10 (0, -5) -> (24.6, -5)
  line L11 (12.3, 5) -> (12.3, -5)
  line L12 (24.6, 5) -> (0, 5)
  line L13 (24.6, 0) -> (0, 0)
  line L14 (51.21, 12.3) -> (0, 12.3)
  line L15 (51.21, -12.3) -> (51.21, 12.3)
  line L16 (0, -12.3) -> (51.21, -12.3)
  line L17 (66, -55) -> (66, 55)
  line L18 (66, 0) -> (51.21, 0)
  line L19 (-34.4247, 0) -> (0, 0)
  line L20 (-34.4247, 4) -> (-18.4247, 4)
  line L21 (-18.4247, -4) -> (-34.4247, -4)
  circle C1 centre (0, 0) radius 10
  circle C2 centre (0, 0) radius 10.3
  arc A1 centre (-34.4247, 0) radius 4 clockwise from (-34.4247, -4) to (-34.4247, 4)
  circle C3 centre (0, 0) radius 12.3
  arc A2 centre (-18.4247, 16.3) radius 12.3 clockwise from (-9.2124, 8.15) to (-18.4247, 4)
  arc A3 centre (-18.4247, -16.3) radius 12.3 clockwise from (-18.4247, -4) to (-9.2124, -8.15)
  arc A4 centre (62, 40) radius 4 clockwise from (58.7574, 42.3421) to (65.0379, 37.3978)
  arc A5 centre (62, -40) radius 4 clockwise from (65.0378, -37.3978) to (58.7574, -42.3421)
  arc A6 centre (0, -84.7809) radius 72.4809 clockwise from (0, -12.3) to (58.7574, -42.3421)
  arc A7 centre (0, 84.7809) radius 72.4809 clockwise from (58.7574, 42.3421) to (0, 12.3)
  arc A8 centre (108.6956, 0) radius 57.4856 clockwise from (65.0378, -37.3978) to (65.0379, 37.3978)
  point P1 (0, 0)
  point P3 (0, 0)
  point P6 (0, 0)
  point P7 (10.3, 0)
  point P20 (24.6, 0)
  point P21 (24.6, -5)
  point P22 (12.3, -5)
  point P24 (24.6, 5)
  point P23 (12.3, 5)
  point P19 (0, 0)
  point P25 (0, 0)
  point P26 (24.6, 0)
  point P27 (0, 12.3)
  point P30 (0, -12.3)
  point P33 (51.21, 0)
  point P34 (66, 0)
  point P35 (0, 0)
  point P16 (-34.4247, 0)
  point P36 (-34.4247, 0)
  point P39 (-9.2124, 8.15)
  point P41 (-9.2124, -8.15)
  point P55 (108.6956, 0)
  point P51 (0, -12.3)
  point P53 (0, 12.3)
  point P47 (58.7574, -42.3421)
  point P50 (58.7574, -42.3421)
  point P45 (58.7574, 42.3421)
  point P54 (58.7574, 42.3421)
  point P44 (65.0379, 37.3978)
  point P56 (65.0379, 37.3978)
  point P48 (65.0378, -37.3978)
  point P57 (65.0378, -37.3978)
  point P2 (0, 0)
  point P18 (-34.4247, -4)
  point P42 (-18.4247, -4)
  point P43 (62, 40)
  point P46 (62, -40)
  coincident P1 P3
  midpoint L1 P6
  coincident P1 P6
  coincident C2 P7
  perpendicular L2 L3
  perpendicular L2 L5
  concentric C2 C3
  vertical L1
  perpendicular L4 L5
  midpoint L2 P20
  coincident L2 P21
  perpendicular L2 L10
  midpoint L10 P22
  perpendicular L10 L11
  vertical L11
  coincident L2 P24
  perpendicular L9 L12
  midpoint P23 L12
  coincident P19 P25
  horizontal L13
  coincident P20 P26
  equal L6 L10
  tangent C3 L11
  tangent C2 L5
  coincident C3 P27
  horizontal L14
  perpendicular L14 L15
  tangent C3 L16
  perpendicular L15 L16
  tangent C3 L14
  coincident C3 P30
  vertical L17
  midpoint L15 P33
  midpoint L17 P34
  perpendicular L17 L18
  coincident P3 P35
  coincident P16 P36
  horizontal L19
  coincident C3 P39
  coincident C3 P41
  tangent A1 L20
  tangent A1 L21
  tangent A3 L21
  tangent A2 L20
  tangent C3 A2
  tangent C3 A3
  equal L20 L21
  equal A2 A3
  parallel L20 L21
  equal A1 A4
  equal A1 A5
  coincident L18 P55
  tangent L16 A6
  tangent L14 A7
  tangent L17 A4
  tangent L17 A5
  tangent L15 A8
  equal C3 A2
  coincident L16 P51
  coincident L14 P53
  coincident P27 P53
  coincident P30 P51
  equal A6 A7
  coincident P47 P50
  tangent A5 A6
  coincident P45 P54
  tangent A4 A7
  coincident P44 P56
  coincident P48 P57
  tangent A5 A8
  dimension "d747" diameter C1 = 20 (= "leadscrew_od")
  dimension "d749" distance C1 C2 = 0.3 (= "clearance_loose")
  dimension "d1302" distance C2 C3 = 2 (= "wall_thickness")
  dimension "d1313" distance L10 L12 = 10 (= "leadscrew_od / 2")
  dimension "d1538" distance L7 L15 = 2 (= "wall_thickness")
  dimension "d1545" distance P2 L17 = 66
  dimension "d1546" radius A1 = 4 (= "2 * wall_thickness")
  dimension "d1548" distance P18 P42 = 16 (= "ptfe_od * 4")
  dimension "d1706" distance P43 P46 = 80
extrude "Extrude2" new body sketch "Sketch1" profile of C2 L2 L3 L4 L5 A1 C3 L10 L12 L13 L14 L15 L16 A2 A3 L20 L21 A4 A5 A6 A7 A8 distance 20 (= "leadscrew_od") bodies "leadscrew_block"
sketch "tooth_hole" plane through (0, 0, 0) normal (1, 0, 0) x axis (0, 0, -1)
  line L1 (-7.2832, 0) -> (-3.6416, -3.6416)
  line L2 (-3.6416, 3.6416) -> (-7.2832, 0)
  line L3 (-10, -10.3) -> (-10, 10.3)
  line L4 (10, 10.3) -> (10, -10.3)
  line L5 (7.2832, 0) -> (3.6416, -3.6416)
  line L6 (-7.2832, 0) -> (7.2832, 0)
  line L7 (3.6416, 3.6416) -> (7.2832, 0)
  line L8 (-10, 10.3) -> (10, 10.3)
  line L9 (10, -10.3) -> (-10, -10.3)
  line L10 (-5.15, 2.1332) -> (-5.15, -2.1332)
  line L11 (5.15, 2.1332) -> (5.15, -2.1332)
  line L12 (-10, -10.3) -> (10, -10.3)
  line L13 (-10, 10.3) -> (-10, -10.3)
  line L14 (10, 10.3) -> (-10, 10.3)
  line L15 (10, -10.3) -> (10, 10.3)
  circle C1 centre (0, 0) radius 5.15
  circle C2 centre (0, 0) radius 5
  point P1 (0, 0)
  point P2 (0, 0)
  point P3 (-3.6416, -3.6416)
  point P5 (-3.6416, 3.6416)
  point P11 (3.6416, -3.6416)
  point P10 (0, 0)
  point P13 (3.6416, 3.6416)
  point P14 (-5.15, -2.1332)
  point P15 (-5.15, 2.1332)
  point P16 (5.15, -2.1332)
  point P17 (5.15, 2.1332)
  coincident P1 P2
  coincident C1 P3
  coincident C1 P5
  tangent C1 L1
  tangent C1 L2
  coincident C1 P11
  midpoint P10 L6
  horizontal L6
  coincident C1 P13
  tangent C1 L5
  tangent C1 L7
  coincident L1 P14
  coincident L2 P15
  vertical L10
  coincident L5 P16
  coincident L7 P17
  tangent C1 L10
  tangent C1 L11
  perpendicular L6 L11
  dimension "d790" distance C1 C2 = 0.15 (= "clearance_loose / 2")
  dimension "d845" angle L1 L6 = 45 (= "overhang_angle")
  dimension "d1420" diameter C2 = 10 (= "leadscrew_od / 2")
extrude "Extrude11" cut sketch "tooth_hole" profile of C1 L1 L2 L5 L7 L10 L11 to an object
sketch "Sketch44" plane through (0, -4, 0) normal (0, -1, 0) x axis (1, 0, 0)
  line L1 (-18.4247, -10) -> (-34.4247, 10)
  line L2 (-18.4247, 10) -> (-18.4247, -10)
  line L3 (-34.4247, 10) -> (-18.4247, 10)
  line L4 (-34.4247, -10) -> (-34.4247, 10)
  line L5 (-18.4247, -10) -> (-34.4247, -10)
  line L6 (-25.9247, 2.3284) -> (-26.9247, 2.3284)
  line L7 (-25.0105, 1.4142) -> (-25.9247, 2.3284)
  line L8 (-26.9247, 2.3284) -> (-27.8389, 1.4142)
  line L9 (-26.9247, -2.3284) -> (-27.8389, -1.4142)
  line L10 (-25.9247, -2.3284) -> (-26.9247, -2.3284)
  line L11 (-25.0105, -1.4142) -> (-25.9247, -2.3284)
  line L12 (-26.4247, -2.3284) -> (-26.4247, 2.3284)
  circle C1 centre (-26.4247, 0) radius 2
  point P2 (-26.4247, 0)
  point P3 (-34.4247, 10)
  point P7 (-34.4247, 10)
  point P4 (-18.4247, -10)
  point P5 (-18.4247, -10)
  point P11 (-25.0105, 1.4142)
  point P12 (-27.8389, 1.4142)
  point P13 (-27.8389, -1.4142)
  point P16 (-25.0105, -1.4142)
  point P17 (-26.4247, 2.3284)
  point P18 (-26.4247, -2.3284)
  point P9 (-26.9247, 2.3284)
  point P10 (-25.9247, 2.3284)
  midpoint P2 L1
  coincident P3 P7
  coincident P4 P5
  horizontal L6
  coincident C1 P11
  coincident C1 P12
  coincident C1 P13
  parallel L6 L10
  coincident C1 P16
  parallel L8 L11
  tangent C1 L8
  tangent C1 L9
  tangent C1 L11
  tangent C1 L7
  midpoint L6 P17
  midpoint L10 P18
  midpoint P2 L12
  equal L7 L8
  dimension "d1539" diameter C1 = 4 (= "ptfe_od")
  dimension "d1551" angle L7 L12 = 45
  dimension "d1552" distance P9 P10 = 1 (= "ptfe_od / 4")
extrude "Extrude27" cut sketch "Sketch44" profile of C1 L6 L7 L8 L9 L10 L11 no distance stored
chamfer "Chamfer5" distance 0.6667 (= "wall_thickness / 3")
coil_primitive "CoilPrimitive1" Diameter 23.3333 (= "leadscrew_od + leadscrew_tooth_height") SectionSize 6.6667 (= "leadscrew_tooth_height * 2") TaperAngle 0 Pitch 30 (= "leadscrew_pitch") Revolutions 0.875 (= "leadscrew_turns / 2 - 1 / 8") bodies "groove"
mirror "Mirror1" mirrorStitchTolerance 0.1
loft "Loft1"
mirror "Mirror2" mirrorStitchTolerance 0.1
extrude "Extrude8" new body sketch "Sketch1" profile of C1 L1 L10 L12 L13 along normal blind 139.172 (= "leadscrew_length - ( leadscrew_center_position + bearing_z / 2 - stack_unit )") and against normal blind 60.828 (= "leadscrew_center_position + bearing_z / 2 - stack_unit") bodies "leadscrew"
combine "Combine7" bodies "groove"
revolve "Revolve1" sketch "Sketch1" AlongAngle 360 bodies "leadscrew_tooth"
extrude "Extrude14" new body sketch "Sketch1" profile of L6 L7 L9 L8 to an object Side2Offset 0 bodies "leadscrew_pin"
fillet "Fillet4" radius 4 (= "wall_thickness * 2")
chamfer "Chamfer3" distance 2 (= "wall_thickness")
move "Move8" RotateAngle 90
move "Move9" TranslateX 0 TranslateY 0 TranslateZ 7.5 (= "leadscrew_pitch / 4")
combine "Combine4"
move "Move6" RotateAngle 180
move "Move10" RotateAngle -128.954 (= "-2 * leadscrew_angle")
combine "Combine6"
sketch "tooth_trim" plane through (0, -24.6, 0) normal (0, 1, 0) x axis (-1, 0, 0)
  line L1 (0, 7.5) -> (4.5121, 9.6544)
  line L2 (-1.122, 9.8499) -> (0, 7.5)
  curve K1 (-1.122, 9.8499) -> (2.7142, 11.6992)
  curve K2 (4.9719, 6.9707) -> (4.5121, 9.6544)
  line L3 (0, 7.5) -> (4.5121, 9.6544)
  line L4 (1.122, 5.1501) -> (0, 7.5)
  curve K3 (4.9719, 6.9707) -> (1.122, 5.1501)
  curve K4 (4.9719, 6.9707) -> (4.5121, 9.6544)
  line L5 (0, 7.5) -> (4.5121, 9.6544)
  curve K5 (4.5121, 9.6544) -> (2.7142, 11.6992)
  line L6 (1.122, 5.1501) -> (0, 7.5)
  curve K6 (4.9719, 6.9707) -> (1.122, 5.1501)
  curve K7 (1.122, 5.1501) -> (-2.7142, 3.3008)
  line L7 (-1.122, 9.8499) -> (0, 7.5)
  curve K8 (-4.9719, 8.0293) -> (-1.122, 9.8499)
  curve K9 (-4.9719, 8.0293) -> (-4.5121, 5.3456)
  line L8 (0, 7.5) -> (-4.5121, 5.3456)
  curve K10 (2.7142, 11.6992) -> (-2.1544, 12.0121)
  curve K11 (4.5121, 9.6544) -> (2.7142, 11.6992)
  curve K12 (4.9719, 6.9707) -> (4.5121, 9.6544)
  curve K13 (2.1544, 2.9879) -> (4.9719, 6.9707)
  curve K14 (-2.7142, 3.3008) -> (2.1544, 2.9879)
  curve K15 (-4.5121, 5.3456) -> (-2.7142, 3.3008)
  curve K16 (-4.9719, 8.0293) -> (-4.5121, 5.3456)
  curve K17 (-2.1544, 12.0121) -> (-4.9719, 8.0293)
  circle C1 centre (0, 7.5) radius 5
extrude "Extrude10" sketch "tooth_trim" profile of K1 K3 K6 K7 no distance stored
shell "Shell3" innerThickness 2 (= "wall_thickness")
copy_paste_bodies "CopyPasteBodies4"
align "Align4"
combine "Combine9" bodies "spur_gear_50t_7mm (1)"
sketch "lathe" plane through (0, 0, 0) normal (0, 1, 0) x axis (1, 0, 0)
  line L1 (30, 25) -> (0, -5)
  line L2 (0, 26.4142) -> (30.5858, 26.4142)
  line L3 (13, 44.8284) -> (30, 27.8284)
  line L4 (13, 56.4284) -> (13, 44.8284)
  line L5 (0, 25) -> (30, 25)
  line L6 (0, 120) -> (0, -120)
  line L7 (13, -44.8284) -> (30, -27.8284)
  line L8 (0, -44.8284) -> (13, -44.8284)
  line L9 (0, 44.8284) -> (13, 44.8284)
  line L10 (10, 63.4284) -> (10, 56.4284)
  line L11 (0, 63.4284) -> (10, 63.4284)
  line L12 (0, -26.4142) -> (30.5858, -26.4142)
  line L13 (0, 56.4284) -> (13, 56.4284)
  line L14 (13, 63.4284) -> (10, 63.4284)
  line L15 (13, 75.0284) -> (13, 63.4284)
  line L16 (0, 75.0284) -> (13, 75.0284)
  line L17 (0, 59.9284) -> (10, 59.9284)
  line L18 (13, 86.6284) -> (13, 75.0284)
  line L19 (0, 86.6284) -> (13, 86.6284)
  line L20 (240, 120) -> (0, 120)
  line L21 (240, -120) -> (240, 120)
  line L22 (0, -120) -> (240, -120)
  line L23 (5, 0) -> (30, -25)
  line L24 (0, -5) -> (5, 0)
  line L25 (0, -25) -> (30, -25)
  line L26 (0, 0) -> (5, 0)
  line L27 (25, -20) -> (25, 20)
  line L28 (175, 120) -> (10.1716, -44.8284)
  line L29 (3.5858, -1.4142) -> (28.5858, -26.4142)
  line L30 (0, -113.3716) -> (13, -113.3716)
  line L31 (10, -52.0711) -> (10, -102.1072)
  line L32 (7.8377, -102.1072) -> (7.8377, -52.0711)
  line L33 (28.5858, 26.4142) -> (0, -2.1716)
  line L34 (10.1716, 44.8284) -> (28.5858, 26.4142)
  line L35 (10, 67.7858) -> (10, 52.0711)
  line L36 (7.8377, 52.0711) -> (7.8377, 67.7858)
  line L37 (10.8377, 86.6284) -> (10.8377, 79.0501)
  line L38 (0, 22) -> (27, 22)
  line L39 (27, -40) -> (27, 22)
  line L40 (0, -111.3716) -> (10.6406, -111.3716)
  line L41 (0, 84.6284) -> (10.8377, 84.6284)
  line L42 (13, -116.0292) -> (13, -113.3716)
  arc A1 centre (28.5858, -26.4142) radius 2 clockwise from (30, -25) to (30, -27.8284)
  arc A2 centre (28.5858, 26.4142) radius 2 clockwise from (30, 27.8284) to (30, 25)
  arc A3 centre (20.2426, -52.0711) radius 10.2426 clockwise from (10, -52.0711) to (13, -44.8284)
  arc A4 centre (20.2426, -52.0711) radius 12.4049 clockwise from (7.8377, -52.0711) to (10.1716, -44.8284)
  arc A5 centre (20.2426, 52.0711) radius 10.2426 clockwise from (13, 44.8284) to (10, 52.0711)
  arc A6 centre (20.2426, 52.0711) radius 12.4049 clockwise from (10.1716, 44.8284) to (7.8377, 52.0711)
  arc A7 centre (20.2426, 67.7858) radius 12.4049 clockwise from (7.8377, 67.7858) to (9.4809, 73.9557)
  arc A8 centre (0.5951, 79.0501) radius 10.2426 clockwise from (10.8377, 79.0501) to (9.4809, 73.9557)
  arc A9 centre (0.5951, 79.0501) radius 12.4049 clockwise from (13, 79.0501) to (11.3568, 72.8802)
  arc A10 centre (20.2426, 67.7858) radius 10.2426 clockwise from (10, 67.7858) to (11.3568, 72.8802)
  arc A11 centre (0.5951, -113.3716) radius 12.4049 clockwise from (11.3568, -107.2017) to (13, -113.3716)
  arc A12 centre (20.2426, -102.1072) radius 10.2426 clockwise from (11.3568, -107.2017) to (10, -102.1072)
  arc A13 centre (0.5951, -113.3716) radius 10.2426 clockwise from (9.4809, -108.2771) to (10.6406, -111.3716)
  arc A14 centre (20.2426, -102.1072) radius 12.4049 clockwise from (9.4809, -108.2771) to (7.8377, -102.1072)
  point P6 (30, 25)
  point P1 (0, 0)
  point P2 (0, 26.4142)
  point P7 (0, 25)
  point P12 (0, -44.8284)
  point P13 (0, 44.8284)
  point P16 (0, 63.4284)
  point P17 (0, -26.4142)
  point P18 (0, 56.4284)
  point P14 (10, 56.4284)
  point P21 (0, 75.0284)
  point P22 (10, 59.9284)
  point P23 (0, 59.9284)
  point P24 (28.5858, -26.4142)
  point P25 (30, -27.8284)
  point P30 (30, -27.8284)
  point P32 (30.5858, 26.4142)
  point P10 (30.5858, -26.4142)
  point P3 (30, 27.8284)
  point P29 (30, 27.8284)
  point P28 (30, 25)
  point P31 (30, 25)
  point P35 (0, 86.6284)
  point P27 (28.5858, 26.4142)
  point P40 (0, -5)
  point P41 (30, -25)
  point P42 (0, -25)
  point P36 (0, -5)
  point P44 (0, 0)
  point P45 (25, 20)
  point P46 (25, -20)
  point P47 (10.1716, -44.8284)
  point P48 (175, 120)
  point P20 (13, 75.0284)
  point P33 (13, 75.0284)
  point P49 (28.5858, -26.4142)
  point P50 (3.5858, -1.4142)
  point P52 (0, -113.3716)
  point P53 (10, -52.0711)
  point P55 (10, -52.0711)
  point P54 (20.2426, -52.0711)
  point P56 (20.2426, -52.0711)
  point P37 (5, 0)
  point P43 (5, 0)
  point P59 (0, -2.1716)
  point P60 (28.5858, 26.4142)
  point P61 (28.5858, 26.4142)
  point P62 (10.1716, 44.8284)
  point P63 (20.2426, 52.0711)
  point P66 (20.2426, 52.0711)
  point P73 (10.8377, 86.6284)
  point P71 (0.5951, 79.0501)
  point P74 (0.5951, 79.0501)
  point P75 (11.3568, 72.8802)
  point P78 (11.3568, 72.8802)
  point P76 (13, 79.0501)
  point P68 (20.2426, 67.7858)
  point P77 (20.2426, 67.7858)
  point P79 (27, 22)
  point P80 (0, 22)
  point P82 (27, -9)
  point P84 (0, -111.3716)
  point P85 (10.8377, 84.6284)
  point P86 (0, 84.6284)
  point P58 (7.8377, -102.1072)
  point P95 (7.8377, -102.1072)
  point P51 (10, -102.1072)
  point P91 (10, -102.1072)
  point P90 (20.2426, -102.1072)
  point P94 (20.2426, -102.1072)
  point P88 (0.5951, -113.3716)
  point P92 (0.5951, -113.3716)
  point P8 (0, -120)
  point P9 (0, 120)
  point P5 (13, 44.8284)
  point P4 (13, 56.4284)
  point P19 (13, 63.4284)
  point P15 (10, 63.4284)
  point P34 (13, 86.6284)
  point P81 (27, -40)
  point P87 (13, -113.3716)
  coincident L1 P6
  vertical L6
  midpoint P1 L6
  perpendicular L2 L6
  coincident P2 L6
  coincident P7 L6
  perpendicular L5 L6
  coincident L6 P12
  perpendicular L6 L8
  coincident L6 P13
  perpendicular L6 L9
  equal L3 L7
  coincident L6 P16
  perpendicular L6 L11
  coincident L6 P17
  perpendicular L6 L12
  equal L2 L12
  equal L8 L9
  coincident L6 P18
  perpendicular L6 L13
  coincident P14 L13
  perpendicular L10 L14
  coincident L6 P21
  perpendicular L6 L16
  perpendicular L15 L16
  perpendicular L4 L13
  midpoint L10 P22
  coincident L6 P23
  perpendicular L6 L17
  coincident L12 P24
  coincident P25 P30
  midpoint A2 P32
  midpoint P10 A1
  coincident P3 P29
  coincident P28 P31
  tangent L3 A2
  coincident L6 P35
  perpendicular L6 L19
  perpendicular L18 L19
  coincident L2 P27
  equal A1 A2
  perpendicular L6 L20
  perpendicular L20 L21
  perpendicular L6 L22
  equal L6 L20
  tangent A1 L23
  coincident L6 P40
  parallel L7 L24
  parallel L3 L23
  coincident L23 P41
  coincident L6 P42
  perpendicular L6 L25
  equal L5 L25
  coincident L6 P36
  coincident P1 P44
  perpendicular L6 L26
  coincident L1 P45
  coincident L23 P46
  vertical L27
  coincident L8 P47
  parallel L7 L28
  coincident L20 P48
  coincident P20 P33
  coincident P24 P49
  coincident L24 P50
  perpendicular L24 L29
  coincident L6 P52
  perpendicular L6 L30
  perpendicular L30 L31
  coincident P53 P55
  tangent L31 A3
  tangent L7 A3
  coincident P54 P56
  perpendicular L30 L32
  tangent A4 L32
  coincident P37 P43
  coincident L1 P37
  coincident L6 P59
  coincident P27 P60
  coincident P27 P61
  coincident L9 P62
  parallel L3 L34
  parallel L1 L33
  tangent A5 L35
  tangent L3 A5
  parallel L6 L35
  collinear L10 L35
  coincident P63 P66
  equal A6 A7
  tangent A7 L36
  tangent A6 L36
  tangent A7 A8
  coincident L19 P73
  perpendicular L19 L37
  tangent A8 L37
  coincident P71 P74
  tangent L10 A10
  coincident P75 P78
  coincident L18 P76
  tangent A9 A10
  tangent L18 A9
  tangent L35 A10
  parallel L35 L36
  coincident P68 P77
  midpoint P22 L35
  equal A8 A10
  coincident L1 P79
  coincident L6 P80
  perpendicular L6 L38
  perpendicular L38 L39
  midpoint L39 P82
  coincident L6 P84
  perpendicular L6 L40
  coincident L37 P85
  coincident L6 P86
  perpendicular L6 L41
  tangent A11 A12
  tangent L31 A12
  tangent L32 A14
  tangent A13 A14
  coincident P58 P95
  coincident P51 P91
  coincident P90 P94
  coincident P88 P92
  equal A12 A13
  equal A8 A12
  tangent A11 L42
  perpendicular L30 L42
  dimension "d597_1" distance P6 P7 = 30 (= "spool_id_max / 2")
  dimension "d604_1" distance P8 P9 = 240 (= "buildplate_limit")
  dimension "d605_1" angle L2 L3 = 45 (= "overhang_angle")
  dimension "d606_1" angle L1 L2 = 45 (= "overhang_angle")
  dimension "d610_1" distance P5 P13 = 13 (= "axle_od / 2")
  dimension "d619_1" distance L6 L10 = 10 (= "spur_gear_diameter_small / 2")
  dimension "d621_1" distance P4 P5 = 11.6 (= "stack_unit")
  dimension "d622_1" distance P19 P20 = 11.6 (= "stack_unit")
  dimension "d624_1" distance L6 L15 = 13 (= "axle_od / 2")
  dimension "d625_1" distance P14 P15 = 7 (= "bearing_z")
  dimension "d654_1" distance L6 P28 = 30 (= "spool_id_max / 2")
  dimension "d693_1" distance P33 P34 = 11.6 (= "stack_unit")
  dimension "d847" radius A2 = 2 (= "fillet_radius")
  dimension "d857" distance L5 L25 = 50 (= "spool_z_min")
  dimension "d876" distance L6 L27 = 25 (= "spool_id_min / 2")
  dimension "d885" distance L7 L28 = 2 (= "wall_thickness")
  dimension "d1708" distance L19 L30 = 200
  dimension "d1709" distance L6 L31 = 10 (= "spur_gear_diameter_small / 2")
  dimension "d1724" distance L17 P45 = 39.9284
  dimension "d1725" distance L6 L39 = 27 (= "spool_id_bambu / 2")
  dimension "d1726" distance P79 P81 = 62 (= "spool_interface_z_bambu")
  dimension "d1728" distance L17 P82 = 68.9284
  dimension "d1729" distance L30 L40 = 2 (= "wall_thickness")
  dimension "d1730" distance L19 L41 = 2 (= "wall_thickness")
  dimension "d1771" distance P52 P87 = 13 (= "axle_od / 2")
sketch "screw" plane through (0, 0, 0) normal (0, 0, 1) x axis (1, 0, 0)
  line L1 (0, -16.625) -> (0, 16.625)
  circle C1 centre (0, 0) radius 16.625
  circle C2 centre (0, 0) radius 14.625
  circle C3 centre (0, 1.625) radius 13
  circle C4 centre (0, 0) radius 11.375
  circle C5 centre (0, 1.625) radius 12.7
  circle C6 centre (0, 1.625) radius 15
  circle C7 centre (0, 1.625) radius 10.7
  point P1 (0, 0)
  point P2 (0, 0)
  point P5 (0, 16.625)
  point P6 (0, -16.625)
  point P4 (0, 1.625)
  point P3 (0, 0)
  point P8 (0, -11.375)
  point P9 (0, 14.625)
  coincident P1 P2
  concentric C1 C2
  coincident C1 P5
  coincident C1 P6
  vertical L1
  coincident P4 L1
  coincident P3 L1
  concentric C1 C4
  coincident L1 P8
  coincident C3 P8
  coincident C4 P8
  coincident L1 P9
  coincident C2 P9
  coincident C3 P9
  concentric C3 C7
  dimension "d878" distance C1 C2 = 2 (= "wall_thickness")
  dimension "d879" distance C2 C4 = 3.25 (= "axle_od / 8")
  dimension "d880" = 2 (= "wall_thickness")
  dimension "d1710" diameter C3 = 26 (= "axle_od")
  dimension "d1711" diameter C1 = 33.25
  dimension "d1712" distance C5 C7 = 2 (= "wall_thickness")
sweep "Sweep2" sketch "screw" TwistAngle 3323.077 (= "( buildplate_limit / axle_od ) * 360 deg") named "d442_1" TaperAngle 0 named "d443_1" bodies "spool_active_bolt"
sweep "Sweep6" sketch "screw" TwistAngle 3323.077 (= "( buildplate_limit / axle_od ) * 360 deg") TaperAngle 0 bodies "nut_negative"
sweep "Sweep7" sketch "screw" TwistAngle 3323.077 (= "( buildplate_limit / axle_od ) * 360 deg") TaperAngle 0 bodies "nut_positive"
sweep "Sweep8" sketch "screw" TwistAngle 3323.077 (= "( 360 * ( buildplate_limit / axle_od ) ) * 1 deg") TaperAngle 0
revolve "Revolve6" sketch "lathe" AlongAngle 360 bodies "spindle_female"
remove_body "RemoveBody35"
revolve "Revolve10" sketch "lathe" AlongAngle 360
revolve "Revolve9" sketch "lathe" AlongAngle 360
combine "Combine28" bodies "nut_negative"
revolve "Revolve11" sketch "lathe" AlongAngle 360
fillet "Fillet6" radius 2 (= "fillet_radius")
chamfer "Chamfer7" distance 2 (= "wall_thickness")
copy_paste_bodies "CopyPasteBodies12"
move "Move5" TranslateX 0 TranslateY 0 TranslateZ 40
revolve "Revolve15" sketch "lathe" AlongAngle 360
revolve "Revolve7" sketch "lathe" AlongAngle 360 bodies "spindle_male_driven"
remove_body "RemoveBody40"
revolve "Revolve8" sketch "lathe" AlongAngle 360 bodies "spool_cap"
revolve "Revolve12" sketch "lathe" AlongAngle 360
combine "Combine30"
copy_paste_bodies "CopyPasteBodies11"
revolve "Revolve14" sketch "lathe" AlongAngle 360
chamfer "Chamfer5" distance 2 (= "wall_thickness")
copy_paste_bodies "CopyPasteBodies10"
align "Align7"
